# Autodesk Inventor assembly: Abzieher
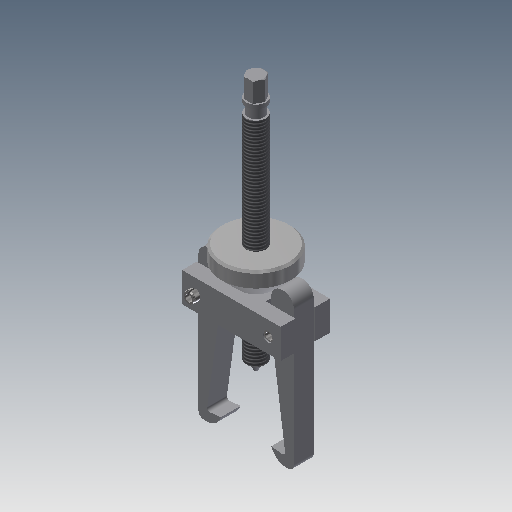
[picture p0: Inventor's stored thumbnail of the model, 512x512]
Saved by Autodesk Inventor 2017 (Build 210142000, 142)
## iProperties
Created: 2015-07
Part Number: Abzieher
Document SubType Name: Assembly
Designer: e_krauts
Author: e_krauts
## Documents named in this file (7)
- C:\Users\e_krauts\Downloads\Abzieher\Abzieher.iam
- C:\Users\e_krauts\Documents\Inventor\Abzieher\Aufnahme.ipt
- C:\Users\e_krauts\Documents\Inventor\Abzieher\Abziehhebel\Abziehhebel_mit_Bohrung-02.ipt
- C:\Users\e_krauts\Documents\Inventor\Abzieher\Abziehhebel.ipt
- C:\Users\e_krauts\Documents\Inventor\Abzieher\ISO 8752 - 5 x 24  (2) DIN EN ISO.ipt
- C:\Users\e_krauts\Documents\Inventor\Abzieher\Konusscheibe.ipt
- C:\Users\e_krauts\Documents\Inventor\Abzieher\Spindel.ipt
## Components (7 placed, 5 different names)
1. Aufnahme:1 — Passend:1, Passend:2, Passend:3, Passend:4, Passend:5, Passend:6, Winkel:1, Winkel:2, Passend:7, Passend:8
2. Abziehhebel_mit_Bohrung-02:1 — Passend:1, Passend:4, Winkel:1
3. Abziehhebel_mit_Bohrung-02:2 — Passend:2, Passend:3, Winkel:2
4. ISO 8752 - 5 x 24  (2) DIN EN ISO:1 — Passend:6
5. ISO 8752 - 5 x 24  (2) DIN EN ISO:2 — Passend:5
6. Konusscheibe:1 — Passend:7, Passend:8, Passend:9
7. Spindel:1 — Passend:9
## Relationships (11: Mate 9, Angle 2)
- Passend:1 [Mate]: Aufnahme:1 ↔ Abziehhebel_mit_Bohrung-02:1
- Passend:2 [Mate]: Aufnahme:1 ↔ Abziehhebel_mit_Bohrung-02:2
- Passend:3 [Mate]: Aufnahme:1 ↔ Abziehhebel_mit_Bohrung-02:2
- Passend:4 [Mate]: Aufnahme:1 ↔ Abziehhebel_mit_Bohrung-02:1
- Passend:5 [Mate]: Aufnahme:1 ↔ ISO 8752 - 5 x 24  (2) DIN EN ISO:2
- Passend:6 [Mate]: Aufnahme:1 ↔ ISO 8752 - 5 x 24  (2) DIN EN ISO:1
- Winkel:1 [Angle]: Aufnahme:1 ↔ Abziehhebel_mit_Bohrung-02:1
- Winkel:2 [Angle]: Aufnahme:1 ↔ Abziehhebel_mit_Bohrung-02:2
- Passend:7 [Mate]: Aufnahme:1 ↔ Konusscheibe:1
- Passend:8 [Mate]: Aufnahme:1 ↔ Konusscheibe:1
- Passend:9 [Mate]: Konusscheibe:1 ↔ Spindel:1
